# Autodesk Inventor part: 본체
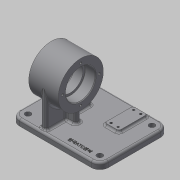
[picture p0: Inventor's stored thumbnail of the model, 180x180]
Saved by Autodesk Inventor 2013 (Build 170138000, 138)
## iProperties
Created: 2019-09
Part Number: 본체
Material: 일반
Document SubType Name: Modeling
Designer: mduedu
Density: 1 g/cm^3
Author: mduedu
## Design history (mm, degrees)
sketch "스케치1"
  geometry: L1 (42, -62)-(-84, -62); L2 (-84, -62)-(-84, 36); L3 (-84, 36)-(42, 36); L4 (42, 36)-(42, -62); 1 further point
  constraints: 8 end point, 2 parallel, 1 horizontal, 1 perpendicular
  dimensions: "d0" = 36 distance from line of L3 point (0, 0); "d1" = 98 distance of L1.end L2.end; "d2" = 42 distance from line of L4 point (0, 0); "d3" = 126 distance of L2.end L3.end
extrude "돌출1" new body sketch "스케치1" distance "d4" = 9; taper "d5" = 0 deg
sketch "스케치2"
  geometry: L1 (0, -62)-(0, 36) reference; C1 r 32 at (59, 0); 1 further point
  constraints: 1 centre point, 1 horizontal alignment
  dimensions: "d6" = 64 diameter of C1; "d7" = 59 distance from line of L1 C1.centre
extrude "돌출2" join sketch "스케치2" stored distance "d8" = 42; taper "d9" = 0 deg
sketch "스케치3"
  geometry: L1 (-17, 4)-(17, 4); L2 (17, 4)-(17, -4); L3 (17, -4)-(-17, -4); L4 (-17, -4)-(-17, 4); L5 (-4, 32)-(4, 32); L6 (4, 32)-(4, -32); L7 (4, -32)-(-4, -32); L8 (-4, -32)-(-4, 32); 5 further points
  constraints: 16 end point, 4 midpoint, 4 parallel, 2 horizontal, 2 horizontal alignment, 2 perpendicular, 2 vertical alignment
  dimensions: "d10" = 8 distance of L5.start L5.end; "d12" = 8 distance of L1.end L2.end; "d13" = 34 distance of L2.end L3.end; "d14" = 64 distance of L5.end L6.end
extrude "돌출3" join sketch "스케치3" stored distance "d15" = 42; taper "d16" = 0 deg
sketch "스케치4"
  geometry: C1 r 32 at (0, 0) reference; C2 r 21 at (0, 0); 1 further point
  constraints: 1 centre point, 1 coincident
  dimensions: "d17" = 42 diameter of C2
extrude "돌출4" cut sketch "스케치4" distance "d18" = 15; taper "d19" = 0 deg
hole "구멍1" diameter "d22" = 36; stored, may be unused: countersink angle "d26" = 90 deg, drill point angle "d28" = 118 deg; dims "d20" = 10, "d21" = 10, "d23" = 6, "d24" = 4, "d25" = 2, "d27" = 8
fillet "모깎기1" dims "d29" = 0.3
chamfer "모따기1" distance "d30" = 1; stored, may be unused: second distance "d31" = 2, angle "d32" = 45 deg
sketch "스케치5" dims "d33" = 52
  geometry: C1 r 32 at (0, 0) reference; 3 further points
  constraints: 2 vertical alignment, 1 coincident, 2 other
hole "구멍2" sketch "스케치5" at (0, 26) diameter "d34" = 3.242; stored, may be unused: countersink angle "d38" = 90 deg, drill point angle "d40" = 118 deg; dims "d35" = 8, "d36" = 4, "d37" = 2, "d39" = 10
fillet "모깎기2" dims "d44" = 12
sketch "스케치6"
  geometry: L1 (-42, 50)-(-42, -24) reference; L2 (-30, -36)-(72, -36) reference; L3 (84, -24)-(84, 50) reference; L4 (72, 62)-(-30, 62) reference; L5 (17, 4)-(17, -4) reference; L6 (17, -4)-(4, -4) reference; L7 (4, -4)-(4, -32) reference; L8 (4, -32)-(-4, -32) reference; L9 (-4, -32)-(-4, -4) reference; L10 (-4, -4)-(-17, -4) reference; L11 (-17, -4)-(-17, 4) reference; L12 (-17, 4)-(-4, 4) reference; L13 (-4, 4)-(-4, 32) reference; L14 (-4, 32)-(4, 32) reference; L15 (4, 32)-(4, 4) reference; L16 (4, 4)-(17, 4) reference; A1 r 12 centre (-30, 50) between (-30, 62) and (-42, 50) reference; A2 r 12 centre (-30, -24) between (-42, -24) and (-30, -36) reference; A3 r 12 centre (72, -24) between (72, -36) and (84, -24) reference; A4 r 12 centre (72, 50) between (84, 50) and (72, 62) reference; 5 further points
  constraints: 4 coincident
hole "구멍3" sketch "스케치6" at (-30, 50), (72, 50), (72, -24), (-30, -24) diameter "d45" = 8; stored, may be unused: countersink angle "d49" = 90 deg, drill point angle "d51" = 118 deg; dims "d46" = 8, "d47" = 4, "d48" = 2, "d50" = 10
sketch "스케치7"
  geometry: L1 (38, 57)-(58, 57); L2 (58, 57)-(58, 17); L3 (58, 17)-(38, 17); L4 (38, 17)-(38, 57); L5 (72, 62)-(-30, 62) reference; 3 further points
  constraints: 8 end point, 2 midpoint, 2 parallel, 1 horizontal, 1 perpendicular
  dimensions: "d52" = 48 horizontal distance of point (48, 57) point (0, 0); "d53" = 20 distance of L1.start L1.end; "d54" = 40 distance of L1.end L2.end; "d55" = 25 distance from line of point (38, 37) L5
extrude "돌출5" join sketch "스케치7" distance "d56" = 3; taper "d57" = 0 deg
fillet "모깎기3" dims "d58" = 3
fillet "모깎기4" dims "d59" = 3
fillet "모깎기5" dims "d60" = 3
fillet "모깎기6" dims "d61" = 3
fillet "모깎기7" dims "d62" = 3
fillet "모깎기8" dims "d63" = 3
sketch "스케치8"
  geometry: L1 (72, 62)-(58.317, 62) reference; L2 (84, -24)-(84, 50) reference; C1 r 1.5 at (43, 53); C2 r 1.5 at (53, 21); 1 further point
  constraints: 2 centre point, 1 equal radius
  dimensions: "d64" = 3 diameter of C1; "d65" = 9 distance from line of C1.centre L1; "d66" = 32 vertical distance of C2.centre C1.centre; "d67" = 10 horizontal distance of C2.centre C1.centre; "d68" = 31 distance from line of L2 C2.centre
hole "구멍4" sketch "스케치8" at (43, 53), (53, 21) diameter "d69" = 3; stored, may be unused: countersink angle "d73" = 90 deg, drill point angle "d75" = 118 deg; dims "d70" = 8, "d71" = 4, "d72" = 2, "d74" = 6
sketch "스케치9"
  geometry: C1 r 1.5 at (43, 53) reference; C2 r 1.5 at (53, 21) reference; 3 further points
  constraints: 2 horizontal alignment, 2 vertical alignment
hole "구멍5" sketch "스케치9" at (53, 53), (43, 21) diameter "d76" = 3.242; stored, may be unused: countersink angle "d80" = 90 deg, drill point angle "d82" = 118 deg; dims "d77" = 6, "d78" = 4, "d79" = 2, "d81" = 8
sketch "스케치10"
  geometry: L1 (-30, -36)-(72, -36) reference; L2 (84, -24)-(84, 50) reference; 2 further points
  constraints: 1 other
  dimensions: "d83" = 10 distance from line of point (46, -26) L1; "d84" = 38 distance from line of point (46, -26) L2
feature "엠보싱1" sketch "스케치10" dims "d0" = 36, "d1" = 98, "d2" = 42, "d3" = 126, "d10" = 8, "d14" = 64, "d85" = 0.5, "d86" = 0
node "솔리드1"
mirror "대칭1"
pattern_circular "원형 패턴1" dims angle "d42" = 360 deg
mirror "대칭2"
node "투영된 루프1"
